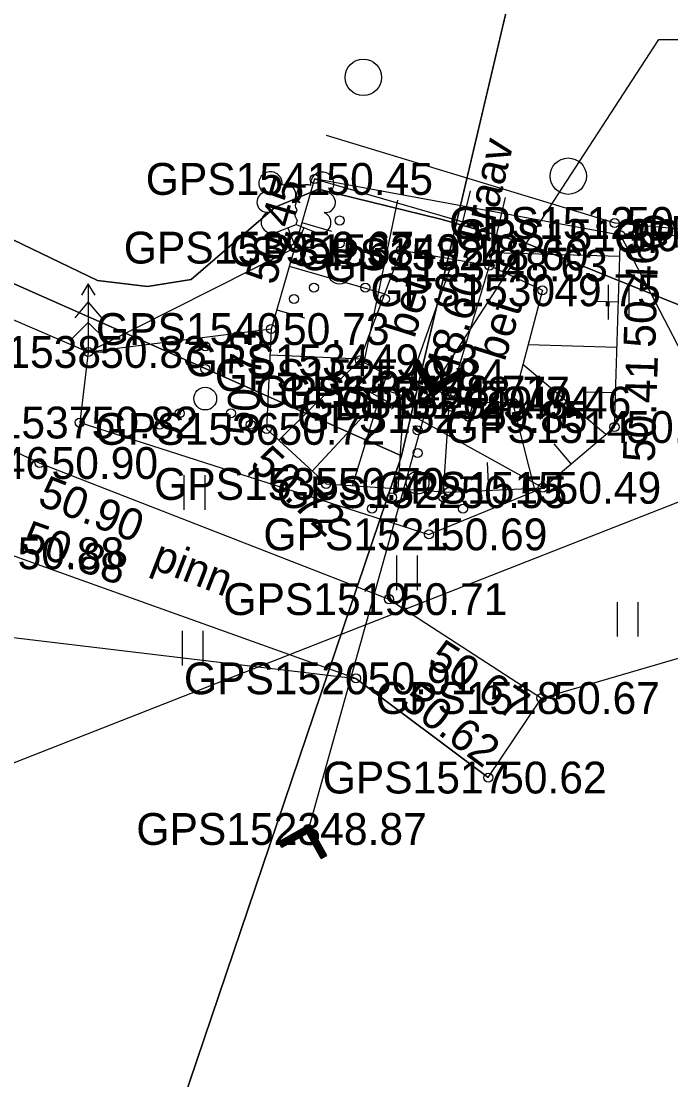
# Model space of a CAD drawing. Extents: x 551623 to 559850, y 6561220 to 6567135.
# Drawn here: x 556553.51 to 556567.79, y 6565132.02 to 6565155.3 of the extents above; entities that cross this region are included whole.
import ezdxf

# ---------------------------------------------------------------- set-up
doc = ezdxf.new("R2010")
doc.units = 0
for name, color, linetype in [('HALJASTUS', 7, 'Continuous'), ('KORGUS-EH2000', 7, 'Continuous'), ('KPOHULIIN', 7, 'Continuous'), ('MOOTKORG-EH2000', 7, 'Continuous'), ('MOOTMPUNKT', 7, 'Continuous'), ('MOOTNR', 7, 'Continuous'), ('MOOTPIIR', 7, 'Continuous'), ('MPKAABEL', 7, 'Continuous'), ('PIIR', 7, 'Continuous'), ('PUU', 7, 'Continuous'), ('RELJEEF', 7, 'Continuous'), ('TEE', 7, 'Continuous'), ('TRUUP', 7, 'Continuous'), ('VEEKOGU', 7, 'Continuous')]:
    doc.layers.add(name, color=color, linetype=linetype)

msp = doc.modelspace()

# ---------------------------------------------------------------- linework, layer by layer
at = {"layer": 'HALJASTUS'}
for p, q in [((556566.682, 6565150.593), (556571.75, 6565140.835)), ((556566.409, 6565149.505), (556566.409, 6565148.744)), ((556566.864, 6565149.505), (556566.864, 6565148.744)), ((556557.089, 6565145.32), (556557.089, 6565144.559)), ((556557.545, 6565145.32), (556557.545, 6565144.559)), ((556561.761, 6565143.552), (556561.761, 6565142.791)), ((556562.216, 6565143.552), (556562.216, 6565142.791)), ((556566.608, 6565142.528), (556566.608, 6565141.767)), ((556567.063, 6565142.528), (556567.063, 6565141.767)), ((556557.052, 6565141.896), (556557.052, 6565141.135)), ((556557.507, 6565141.896), (556557.507, 6565141.135))]:
    msp.add_line(p, q, dxfattribs=at)
for points in [[(556560.214, 6565152.796), (556566.555, 6565150.865), (556570.04, 6565150.556), (556579.273, 6565154.176), (556604.291, 6565163.073), (556630.484, 6565174.696), (556655.692, 6565185.071), (556676.45, 6565195.172), (556699.828, 6565206.048), (556722.286, 6565214.456), (556752.299, 6565224.302), (556776.314, 6565234.412), (556799.911, 6565243.207), (556817.364, 6565249.633), (556836.836, 6565258.911)], [(556559.548, 6565150.322), (556554.988, 6565148.026), (556554.799, 6565146.475), (556562.474, 6565144.016), (556564.975, 6565145.041), (556560.938, 6565147.273), (556561.786, 6565151.363)]]:
    msp.add_lwpolyline(points, dxfattribs=at)
for centre, radius in [((556561.03, 6565154.066), 0.4), ((556565.534, 6565151.894), 0.4), ((556560.51, 6565150.918), 0.1), ((556560.51, 6565150.418), 0.1), ((556560.51, 6565149.768), 0.25), ((556559.945, 6565149.443), 0.1), ((556561.075, 6565149.443), 0.1), ((556559.51, 6565149.193), 0.1), ((556561.51, 6565149.193), 0.1), ((556557.558, 6565148.152), 0.1), ((556557.558, 6565147.652), 0.1), ((556557.558, 6565147.002), 0.25), ((556556.993, 6565146.677), 0.1), ((556558.123, 6565146.677), 0.1), ((556556.558, 6565146.427), 0.1), ((556558.558, 6565146.427), 0.1), ((556562.223, 6565146.304), 0.1), ((556562.223, 6565145.804), 0.1), ((556562.223, 6565145.154), 0.25), ((556561.658, 6565144.829), 0.1), ((556562.788, 6565144.829), 0.1), ((556561.223, 6565144.579), 0.1), ((556563.223, 6565144.579), 0.1)]:
    msp.add_circle(centre, radius, dxfattribs=at)
at = {"layer": 'KORGUS-EH2000'}
for centre in [(556559.96, 6565151.833), (556566.682, 6565150.593), (556559.548, 6565150.322), (556561.863, 6565150.266), (556563.375, 6565150.175), (556559.005, 6565148.531), (556554.799, 6565146.475), (556566.551, 6565146.376), (556558.907, 6565146.335), (556553.919, 6565145.585), (556564.947, 6565140.416), (556563.777, 6565138.667)]:
    msp.add_circle(centre, 0.1, dxfattribs=at)
at = {"layer": 'KPOHULIIN'}
msp.add_lwpolyline([(556534.631, 6565146.039), (556550.784, 6565137.989), (556573.361, 6565146.85), (556606.789, 6565160.281), (556655.904, 6565180.147), (556702.486, 6565198.719), (556702.486, 6565198.719), (556755.324, 6565220.022), (556800.207, 6565237.954), (556845.124, 6565255.757), (556845.124, 6565255.757), (556885.115, 6565272.075)], dxfattribs=at)
at = {"layer": 'MOOTMPUNKT'}
for centre in [(556559.96, 6565151.833), (556566.555, 6565150.865), (556566.682, 6565150.593), (556559.548, 6565150.322), (556561.863, 6565150.266), (556563.375, 6565150.175), (556563.803, 6565149.929), (556564.967, 6565149.384), (556559.005, 6565148.531), (556554.988, 6565148.026), (556560.958, 6565147.844), (556561.546, 6565147.519), (556562.512, 6565147.153), (556562.966, 6565147.135), (556563.449, 6565146.913), (556564.319, 6565146.912), (556563.357, 6565146.598), (556554.799, 6565146.475), (556566.551, 6565146.376), (556558.907, 6565146.335), (556553.919, 6565145.585), (556560.214, 6565145.126), (556564.975, 6565145.041), (556562.91, 6565144.944), (556562.474, 6565144.016), (556561.595, 6565142.591), (556560.868, 6565140.849), (556564.947, 6565140.416), (556563.777, 6565138.667), (556559.823, 6565137.536)]:
    msp.add_circle(centre, 0.1, dxfattribs=at)
at = {"layer": 'MOOTPIIR'}
for points in [[(556752.299, 6565224.302), (556722.286, 6565214.456), (556699.828, 6565206.048), (556676.45, 6565195.172), (556655.692, 6565185.071), (556630.484, 6565174.696), (556604.291, 6565163.073), (556579.273, 6565154.176), (556570.04, 6565150.556), (556566.682, 6565150.593), (556559.96, 6565151.833), (556559.005, 6565148.531), (556554.988, 6565148.026), (556532.572, 6565157.699), (556503.633, 6565171.674), (556471.481, 6565186.145), (556450.892, 6565195.194), (556444.303, 6565198.685), (556419.033, 6565208.861)], [(556436.48, 6565194.185), (556449.647, 6565188.215), (556486.494, 6565172.264), (556501.317, 6565164.974), (556534.661, 6565148.753), (556550.886, 6565142.039), (556560.868, 6565140.849), (556563.777, 6565138.667), (556564.947, 6565140.416), (556574.124, 6565143.095), (556582.549, 6565147.264), (556608.526, 6565156.509), (556634.616, 6565167.336), (556657.454, 6565177.431), (556678.781, 6565185.856), (556704.754, 6565195.238), (556727.607, 6565205.59), (556758.128, 6565217.782)]]:
    msp.add_lwpolyline(points, dxfattribs=at)
at = {"layer": 'MPKAABEL'}
for points in [[(556506.182, 6565171.529), (556508.757, 6565170.404), (556518.017, 6565166.315), (556527.019, 6565162.424), (556534.74, 6565158.962), (556542.186, 6565155.587), (556547.057, 6565153.582), (556552.098, 6565151.085), (556555.187, 6565149.599), (556556.286, 6565149.468), (556557.249, 6565149.621), (556559.094, 6565151.215), (556560.049, 6565151.605), (556562.737, 6565150.949), (556564.659, 6565150.397), (556567.98, 6565149.054), (556571.48, 6565147.45), (556573.066, 6565147.26), (556573.361, 6565146.85)], [(556573.361, 6565146.85), (556573.066, 6565147.26), (556571.48, 6565147.45), (556567.98, 6565149.054), (556564.659, 6565150.397), (556562.737, 6565150.949), (556560.049, 6565151.605), (556559.094, 6565151.215), (556557.249, 6565149.621), (556556.286, 6565149.468), (556555.187, 6565149.599), (556552.098, 6565151.085), (556547.057, 6565153.582), (556542.186, 6565155.587), (556534.74, 6565158.962)]]:
    msp.add_lwpolyline(points, dxfattribs=at)
at = {"layer": 'PIIR'}
for points in [[(556217.39, 6565298.59), (556213.87, 6565303.19), (556229.81, 6565311.25), (556335.44, 6565331.24), (556350.73, 6565342.07), (556507.54, 6565334), (556519.21, 6565368.05), (556548.5, 6565368.1), (556612.15, 6565380.04), (556615.14, 6565380.2), (556613.56, 6565366.23), (556611.32, 6565356.67), (556591.74, 6565273.2), (556570.09, 6565180.67), (556561.87, 6565145.74), (556557.67, 6565147.61), (556393.49, 6565220.36)], [(556393.49, 6565220.36), (556557.67, 6565147.61), (556561.87, 6565145.74), (556518.27, 6565016.8), (556485.25, 6564921.4), (556406.78, 6564699.5), (556400.89, 6564700.63), (556129.6, 6564752.43), (556228.34, 6565008.72), (556274.8, 6564990.28)], [(556570.09, 6565180.67), (557111.29, 6565052.74), (557117.08, 6565090.14), (557118.41, 6565095.6), (557901.49, 6564929.97), (557785.81, 6564832.39), (557095.9, 6564977.82), (557081.84, 6564912.06), (557074.86, 6564913.78), (556985.4, 6564932.84), (556549.21, 6565025.4), (556543.91, 6565008.61), (556523.04, 6565015.28), (556518.27, 6565016.8), (556561.87, 6565145.74)]]:
    msp.add_lwpolyline(points, close=True, dxfattribs=at)
at = {"layer": 'PUU'}
for p, q in [((556559.108, 6565150.657), (556559.553, 6565150.832)), ((556559.548, 6565150.322), (556559.373, 6565150.762)), ((556559.548, 6565150.322), (556559.728, 6565150.762)), ((556559.553, 6565150.832), (556559.993, 6565150.652)), ((556559.928, 6565150.322), (556559.548, 6565150.322)), ((556554.988, 6565149.526), (556554.838, 6565149.276)), ((556555.138, 6565149.276), (556554.988, 6565149.526)), ((556554.988, 6565149.526), (556554.988, 6565148.026)), ((556554.988, 6565149.127), (556554.688, 6565148.776)), ((556555.288, 6565148.776), (556554.988, 6565149.127)), ((556554.988, 6565148.677), (556554.588, 6565148.276)), ((556555.388, 6565148.276), (556554.988, 6565148.677)), ((556555.348, 6565148.026), (556554.988, 6565148.026))]:
    msp.add_line(p, q, dxfattribs=at)
msp.add_lwpolyline([(556559.553, 6565151.327), (556559.533, 6565151.252), (556559.533, 6565151.232), (556559.543, 6565151.202), (556559.563, 6565151.167), (556559.568, 6565151.147), (556559.553, 6565151.112), (556559.528, 6565151.062), (556559.523, 6565151.037), (556559.528, 6565151.022), (556559.538, 6565150.992), (556559.573, 6565150.932), (556559.578, 6565150.912), (556559.573, 6565150.892), (556559.558, 6565150.857), (556559.553, 6565150.832)], dxfattribs=at)
for centre, radius, start, end in [((556558.991, 6565151.736), 0.256, 111.5027, 232.5173), ((556558.991, 6565151.736), 0.256, 350.4856, 111.5002), ((556560.127, 6565151.728), 0.256, 67.6168, 188.6314), ((556560.127, 6565151.728), 0.256, 306.5997, 67.6143), ((556559.326, 6565151.486), 0.224, 308.5041, 111.5725), ((556559.789, 6565151.481), 0.225, 67.7016, 230.5126), ((556558.917, 6565151.325), 0.224, 111.4304, 274.4987), ((556560.194, 6565151.315), 0.224, 264.6183, 67.6866), ((556559.552, 6565151.089), 0.237, 66.7655, 111.5015), ((556559.022, 6565150.881), 0.237, 111.5014, 291.5004), ((556560.083, 6565150.872), 0.237, 247.6166, 67.6155)]:
    msp.add_arc(centre, radius, start, end, dxfattribs=at)
at = {"layer": 'RELJEEF'}
for p, q in [((556559.96, 6565151.833), (556563.215, 6565150.892)), ((556559.682, 6565150.872), (556560.334, 6565150.684)), ((556566.668, 6565150.124), (556563.87, 6565150.211)), ((556559.404, 6565149.911), (556561.504, 6565149.305)), ((556566.636, 6565149.124), (556566.119, 6565149.14)), ((556559.127, 6565148.951), (556559.735, 6565148.775)), ((556566.605, 6565148.125), (556564.653, 6565148.186)), ((556558.98, 6565147.968), (556560.971, 6565147.88)), ((556559.175, 6565146.087), (556560.958, 6565147.844)), ((556566.36, 6565146.214), (556564.539, 6565147.752)), ((556560.797, 6565145.086), (556561.446, 6565147.207)), ((556566.574, 6565147.125), (556565.92, 6565147.146)), ((556559.909, 6565145.408), (556561.138, 6565146.736)), ((556562.793, 6565144.952), (556562.913, 6565146.739)), ((556564.79, 6565145.032), (556564.319, 6565146.912)), ((556561.795, 6565145.019), (556561.9, 6565146.579)), ((556565.597, 6565145.567), (556565.224, 6565146.008)), ((556563.792, 6565144.985), (556563.763, 6565145.594))]:
    msp.add_line(p, q, dxfattribs=at)
msp.add_lwpolyline([(556559.96, 6565151.833), (556559.005, 6565148.531), (556558.907, 6565146.335), (556560.214, 6565145.126), (556562.91, 6565144.944), (556564.975, 6565145.041), (556566.551, 6565146.376), (556566.682, 6565150.593)], dxfattribs=at)
at = {"layer": 'TEE'}
for points in [[(556563.777, 6565138.667), (556560.868, 6565140.849), (556553.174, 6565143.6), (556545.589, 6565147.013), (556535.182, 6565151.57), (556522.842, 6565156.959), (556502.184, 6565166.778), (556486.192, 6565174.091), (556471.011, 6565180.892), (556450.062, 6565190.454), (556440.995, 6565194.267), (556416.948, 6565204.811), (556405, 6565210.263), (556380.262, 6565220.954), (556359.747, 6565229.991), (556339.784, 6565238.7), (556330.661, 6565242.666), (556318.495, 6565248.069), (556305.998, 6565253.52), (556294.082, 6565258.94), (556276.195, 6565266.757), (556256.289, 6565275.582), (556232.166, 6565286.787), (556209.59, 6565295.964)], [(556451.044, 6565192.394), (556472.021, 6565182.87), (556487.128, 6565176.233), (556503.051, 6565168.872), (556523.576, 6565158.838), (556536.005, 6565153.683), (556546.609, 6565149.031), (556553.919, 6565145.585), (556561.595, 6565142.591), (556564.947, 6565140.416)], [(556561.546, 6565147.519), (556560.958, 6565147.844), (556561.863, 6565150.266), (556563.803, 6565149.929), (556564.967, 6565149.384), (556564.319, 6565146.912), (556563.449, 6565146.913)]]:
    msp.add_lwpolyline(points, dxfattribs=at)
at = {"layer": 'TRUUP'}
for p, q in [((556562.242, 6565147.857), (556562.118, 6565147.788)), ((556562.241, 6565147.857), (556562.256, 6565147.543)), ((556562.242, 6565147.857), (556562.554, 6565147.303)), ((556562.118, 6565147.788), (556562.5, 6565147.109)), ((556562.144, 6565147.802), (556562.147, 6565147.737)), ((556562.168, 6565147.816), (556562.174, 6565147.688)), ((556562.18, 6565147.823), (556562.527, 6565147.206)), ((556562.192, 6565147.829), (556562.201, 6565147.64)), ((556562.217, 6565147.843), (556562.228, 6565147.592)), ((556562.268, 6565147.811), (556562.283, 6565147.495)), ((556562.296, 6565147.762), (556562.31, 6565147.446)), ((556562.323, 6565147.714), (556562.337, 6565147.398)), ((556562.35, 6565147.666), (556562.365, 6565147.349)), ((556562.377, 6565147.617), (556562.392, 6565147.301)), ((556562.405, 6565147.569), (556562.419, 6565147.253)), ((556562.432, 6565147.52), (556562.446, 6565147.204)), ((556562.459, 6565147.472), (556562.474, 6565147.156)), ((556562.486, 6565147.423), (556562.501, 6565147.11)), ((556562.5, 6565147.109), (556563.178, 6565147.491)), ((556562.527, 6565147.206), (556563.143, 6565147.553)), ((556562.554, 6565147.303), (556563.108, 6565147.615)), ((556562.713, 6565147.393), (556562.72, 6565147.234)), ((556562.737, 6565147.407), (556562.745, 6565147.247)), ((556562.762, 6565147.42), (556562.769, 6565147.261)), ((556562.786, 6565147.434), (556562.793, 6565147.275)), ((556562.811, 6565147.448), (556562.818, 6565147.288)), ((556562.835, 6565147.461), (556562.842, 6565147.302)), ((556562.859, 6565147.475), (556562.867, 6565147.316)), ((556562.884, 6565147.489), (556562.891, 6565147.33)), ((556562.908, 6565147.503), (556562.915, 6565147.343)), ((556562.932, 6565147.516), (556562.94, 6565147.357)), ((556562.957, 6565147.53), (556562.964, 6565147.371)), ((556562.981, 6565147.544), (556562.989, 6565147.385)), ((556563.006, 6565147.558), (556563.013, 6565147.398)), ((556563.03, 6565147.571), (556563.037, 6565147.412)), ((556563.054, 6565147.585), (556563.062, 6565147.426)), ((556563.079, 6565147.599), (556563.086, 6565147.44)), ((556563.103, 6565147.613), (556563.111, 6565147.453)), ((556563.108, 6565147.615), (556563.178, 6565147.491)), ((556563.13, 6565147.576), (556563.135, 6565147.467)), ((556563.157, 6565147.528), (556563.159, 6565147.481)), ((556562.527, 6565147.206), (556559.823, 6565137.536)), ((556562.514, 6565147.375), (556562.525, 6565147.124)), ((556562.541, 6565147.327), (556562.55, 6565147.137)), ((556562.567, 6565147.31), (556562.574, 6565147.151)), ((556562.591, 6565147.324), (556562.598, 6565147.165)), ((556562.615, 6565147.338), (556562.623, 6565147.179)), ((556562.64, 6565147.352), (556562.647, 6565147.192)), ((556562.664, 6565147.365), (556562.671, 6565147.206)), ((556562.689, 6565147.379), (556562.696, 6565147.22)), ((556559.85, 6565137.633), (556559.172, 6565137.251)), ((556559.809, 6565137.416), (556559.801, 6565137.605)), ((556559.837, 6565137.367), (556559.825, 6565137.619)), ((556559.864, 6565137.319), (556559.849, 6565137.632)), ((556560.232, 6565136.955), (556559.85, 6565137.633)), ((556559.823, 6565137.536), (556559.207, 6565137.189)), ((556559.796, 6565137.439), (556559.242, 6565137.127)), ((556559.393, 6565137.212), (556559.386, 6565137.371)), ((556559.418, 6565137.226), (556559.41, 6565137.385)), ((556559.442, 6565137.24), (556559.435, 6565137.399)), ((556559.466, 6565137.253), (556559.459, 6565137.413)), ((556559.491, 6565137.267), (556559.483, 6565137.426)), ((556559.515, 6565137.281), (556559.508, 6565137.44)), ((556559.54, 6565137.295), (556559.532, 6565137.454)), ((556559.564, 6565137.308), (556559.557, 6565137.467)), ((556559.588, 6565137.322), (556559.581, 6565137.481)), ((556559.613, 6565137.336), (556559.605, 6565137.495)), ((556559.637, 6565137.349), (556559.63, 6565137.509)), ((556559.662, 6565137.363), (556559.654, 6565137.522)), ((556559.686, 6565137.377), (556559.679, 6565137.536)), ((556559.71, 6565137.391), (556559.703, 6565137.55)), ((556559.735, 6565137.404), (556559.727, 6565137.564)), ((556559.759, 6565137.418), (556559.752, 6565137.577)), ((556559.783, 6565137.432), (556559.776, 6565137.591)), ((556560.108, 6565136.885), (556559.796, 6565137.439)), ((556560.17, 6565136.92), (556559.823, 6565137.536)), ((556559.891, 6565137.27), (556559.876, 6565137.586)), ((556559.918, 6565137.222), (556559.904, 6565137.538)), ((556559.946, 6565137.174), (556559.931, 6565137.49)), ((556559.973, 6565137.125), (556559.958, 6565137.441)), ((556560, 6565137.077), (556559.985, 6565137.393)), ((556559.242, 6565137.127), (556559.172, 6565137.251)), ((556559.193, 6565137.214), (556559.191, 6565137.261)), ((556559.22, 6565137.166), (556559.215, 6565137.275)), ((556559.247, 6565137.13), (556559.239, 6565137.289)), ((556559.271, 6565137.143), (556559.264, 6565137.303)), ((556559.296, 6565137.157), (556559.288, 6565137.316)), ((556559.32, 6565137.171), (556559.313, 6565137.33)), ((556559.344, 6565137.185), (556559.337, 6565137.344)), ((556559.369, 6565137.198), (556559.361, 6565137.358)), ((556560.027, 6565137.028), (556560.013, 6565137.344)), ((556560.055, 6565136.98), (556560.04, 6565137.296)), ((556560.082, 6565136.931), (556560.067, 6565137.248)), ((556560.109, 6565136.885), (556560.095, 6565137.199)), ((556560.133, 6565136.899), (556560.122, 6565137.151)), ((556560.108, 6565136.885), (556560.232, 6565136.955)), ((556560.158, 6565136.913), (556560.149, 6565137.102)), ((556560.182, 6565136.927), (556560.176, 6565137.054)), ((556560.207, 6565136.94), (556560.204, 6565137.005))]:
    msp.add_line(p, q, dxfattribs=at)
msp.add_lwpolyline([(556562.527, 6565147.206), (556567.528, 6565154.902), (556573.585, 6565154.902)], dxfattribs=at)
msp.add_lwpolyline([(556561.546, 6565147.519), (556563.449, 6565146.913), (556563.349, 6565146.6), (556561.446, 6565147.207)], close=True, dxfattribs=at)
at = {"layer": 'VEEKOGU'}
for points in [[(556562.052, 6565147.357), (556563.011, 6565150.066), (556563.383, 6565151.57)], [(556562.947, 6565147.072), (556563.803, 6565149.929), (556564.159, 6565151.425)]]:
    msp.add_lwpolyline(points, dxfattribs=at)

# ---------------------------------------------------------------- texts
at = {"layer": 'KORGUS-EH2000'}
for s, rotation, p in [(' 50.45', 73.882, (556559.022, 6565149.226)), (' 50.46', 88.2112, (556567.438, 6565147.854)), (' 48.60', 74.0633, (556562.97, 6565147.171)), (' 50.73', 87.4448, (556558.71, 6565145.917)), (' 50.41', 88.2112, (556567.425, 6565145.334)), (' 50.72', 317.2193, (556558.313, 6565145.692)), (' 50.90', 338.6888, (556553.601, 6565144.77)), (' 50.88', 340.3233, (556553.233, 6565143.765)), (' 50.67', 327.031, (556562.189, 6565141.294)), (' 50.62', 323.1254, (556561.6, 6565140.419))]:
    msp.add_text(s, height=0.7, rotation=rotation, dxfattribs=at).set_placement(p)
msp.add_text(' 50.82', height=0.7, dxfattribs=at).set_placement((556554.799, 6565146.125))
at = {"layer": 'MOOTKORG-EH2000'}
for s, p in [(' 50.45', (556559.96, 6565151.483)), (' 50.40', (556566.555, 6565150.515)), (' 50.46', (556566.682, 6565150.243)), (' 50.67', (556559.548, 6565149.972)), (' 49.18', (556561.863, 6565149.916)), (' 48.60', (556563.375, 6565149.825)), (' 48.63', (556563.803, 6565149.579)), (' 49.75', (556564.967, 6565149.034)), (' 50.73', (556559.005, 6565148.181)), (' 50.83', (556554.988, 6565147.677)), (' 49.63', (556560.958, 6565147.494)), (' 49.84', (556561.546, 6565147.169)), (' 48.71', (556562.512, 6565146.803)), (' 48.77', (556562.966, 6565146.785)), (' 49.84', (556563.449, 6565146.563)), (' 49.46', (556564.319, 6565146.562)), (' 49.85', (556563.357, 6565146.248)), (' 50.82', (556554.799, 6565146.125)), (' 50.72', (556558.907, 6565145.985)), (' 50.41', (556566.551, 6565146.026)), (' 50.90', (556553.919, 6565145.235)), (' 50.70', (556560.214, 6565144.775)), (' 50.55', (556562.91, 6565144.594)), (' 50.49', (556564.975, 6565144.69)), (' 50.69', (556562.474, 6565143.666)), (' 50.88', (556553.174, 6565143.25)), (' 50.71', (556561.595, 6565142.241)), (' 50.91', (556560.868, 6565140.499)), (' 50.67', (556564.947, 6565140.066)), (' 50.62', (556563.777, 6565138.317)), (' 48.87', (556559.823, 6565137.186))]:
    msp.add_text(s, height=0.7, dxfattribs=at).set_placement(p)
at = {"layer": 'MOOTNR'}
for s, p in [('GPS1541 ', (556556.25, 6565151.483)), ('GPS1512 ', (556562.916, 6565150.515)), ('GPS1513 ', (556563.043, 6565150.243)), ('GPS1511 ', (556566.54, 6565150.206)), ('GPS1510 ', (556567.05, 6565150.321)), ('GPS1539 ', (556555.768, 6565149.972)), ('GPS1533 ', (556558.083, 6565149.916)), ('GPS1532 ', (556559.595, 6565149.825)), ('GPS1531 ', (556560.163, 6565149.579)), ('GPS1530 ', (556561.187, 6565149.034)), ('GPS1540 ', (556555.156, 6565148.181)), ('GPS1538 ', (556551.209, 6565147.677)), ('GPS1534 ', (556557.108, 6565147.494)), ('GPS1525 ', (556557.766, 6565147.169)), ('GPS1524 ', (556558.662, 6565146.803)), ('GPS1528 ', (556559.186, 6565146.785)), ('GPS1526 ', (556559.669, 6565146.563)), ('GPS1529 ', (556560.54, 6565146.562)), ('GPS1527 ', (556559.577, 6565146.248)), ('GPS1537 ', (556551.019, 6565146.125)), ('GPS1536 ', (556555.128, 6565145.985)), ('GPS1514 ', (556562.841, 6565146.026)), ('GPS1546 ', (556550.069, 6565145.235)), ('GPS1535 ', (556556.434, 6565144.775)), ('GPS1522 ', (556559.13, 6565144.594)), ('GPS1515 ', (556561.335, 6565144.69)), ('GPS1521 ', (556558.835, 6565143.666)), ('GPS1519 ', (556557.955, 6565142.241)), ('GPS1520 ', (556557.089, 6565140.499)), ('GPS1518 ', (556561.307, 6565140.066)), ('GPS1517 ', (556560.137, 6565138.317)), ('GPS1523 ', (556556.043, 6565137.186))]:
    msp.add_text(s, height=0.7, dxfattribs=at).set_placement(p)
at = {"layer": 'TEE'}
for s, rotation, p in [('bet', 72.5776, (556562.151, 6565148.306)), ('bet', 72.5776, (556564.135, 6565147.798)), ('pinn', 338.8547, (556556.342, 6565143.279))]:
    msp.add_text(s, height=0.7, rotation=rotation, dxfattribs=at).set_placement(p)
at = {"layer": 'VEEKOGU'}
msp.add_text('kraav', height=0.7, rotation=76.5538, dxfattribs=at).set_placement((556563.807, 6565150.398))

doc.saveas('drawing.dxf')
